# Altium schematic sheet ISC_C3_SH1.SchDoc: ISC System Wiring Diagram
size B; DrawnBy: Filiberto Clara; Engineer: Filiberto Clara; Organization: LIGO Laboratory; Address1: California Institute of Technology; Address2: Massachusetts Institute of Technology; SheetNumber: 5; SheetTotal: 39
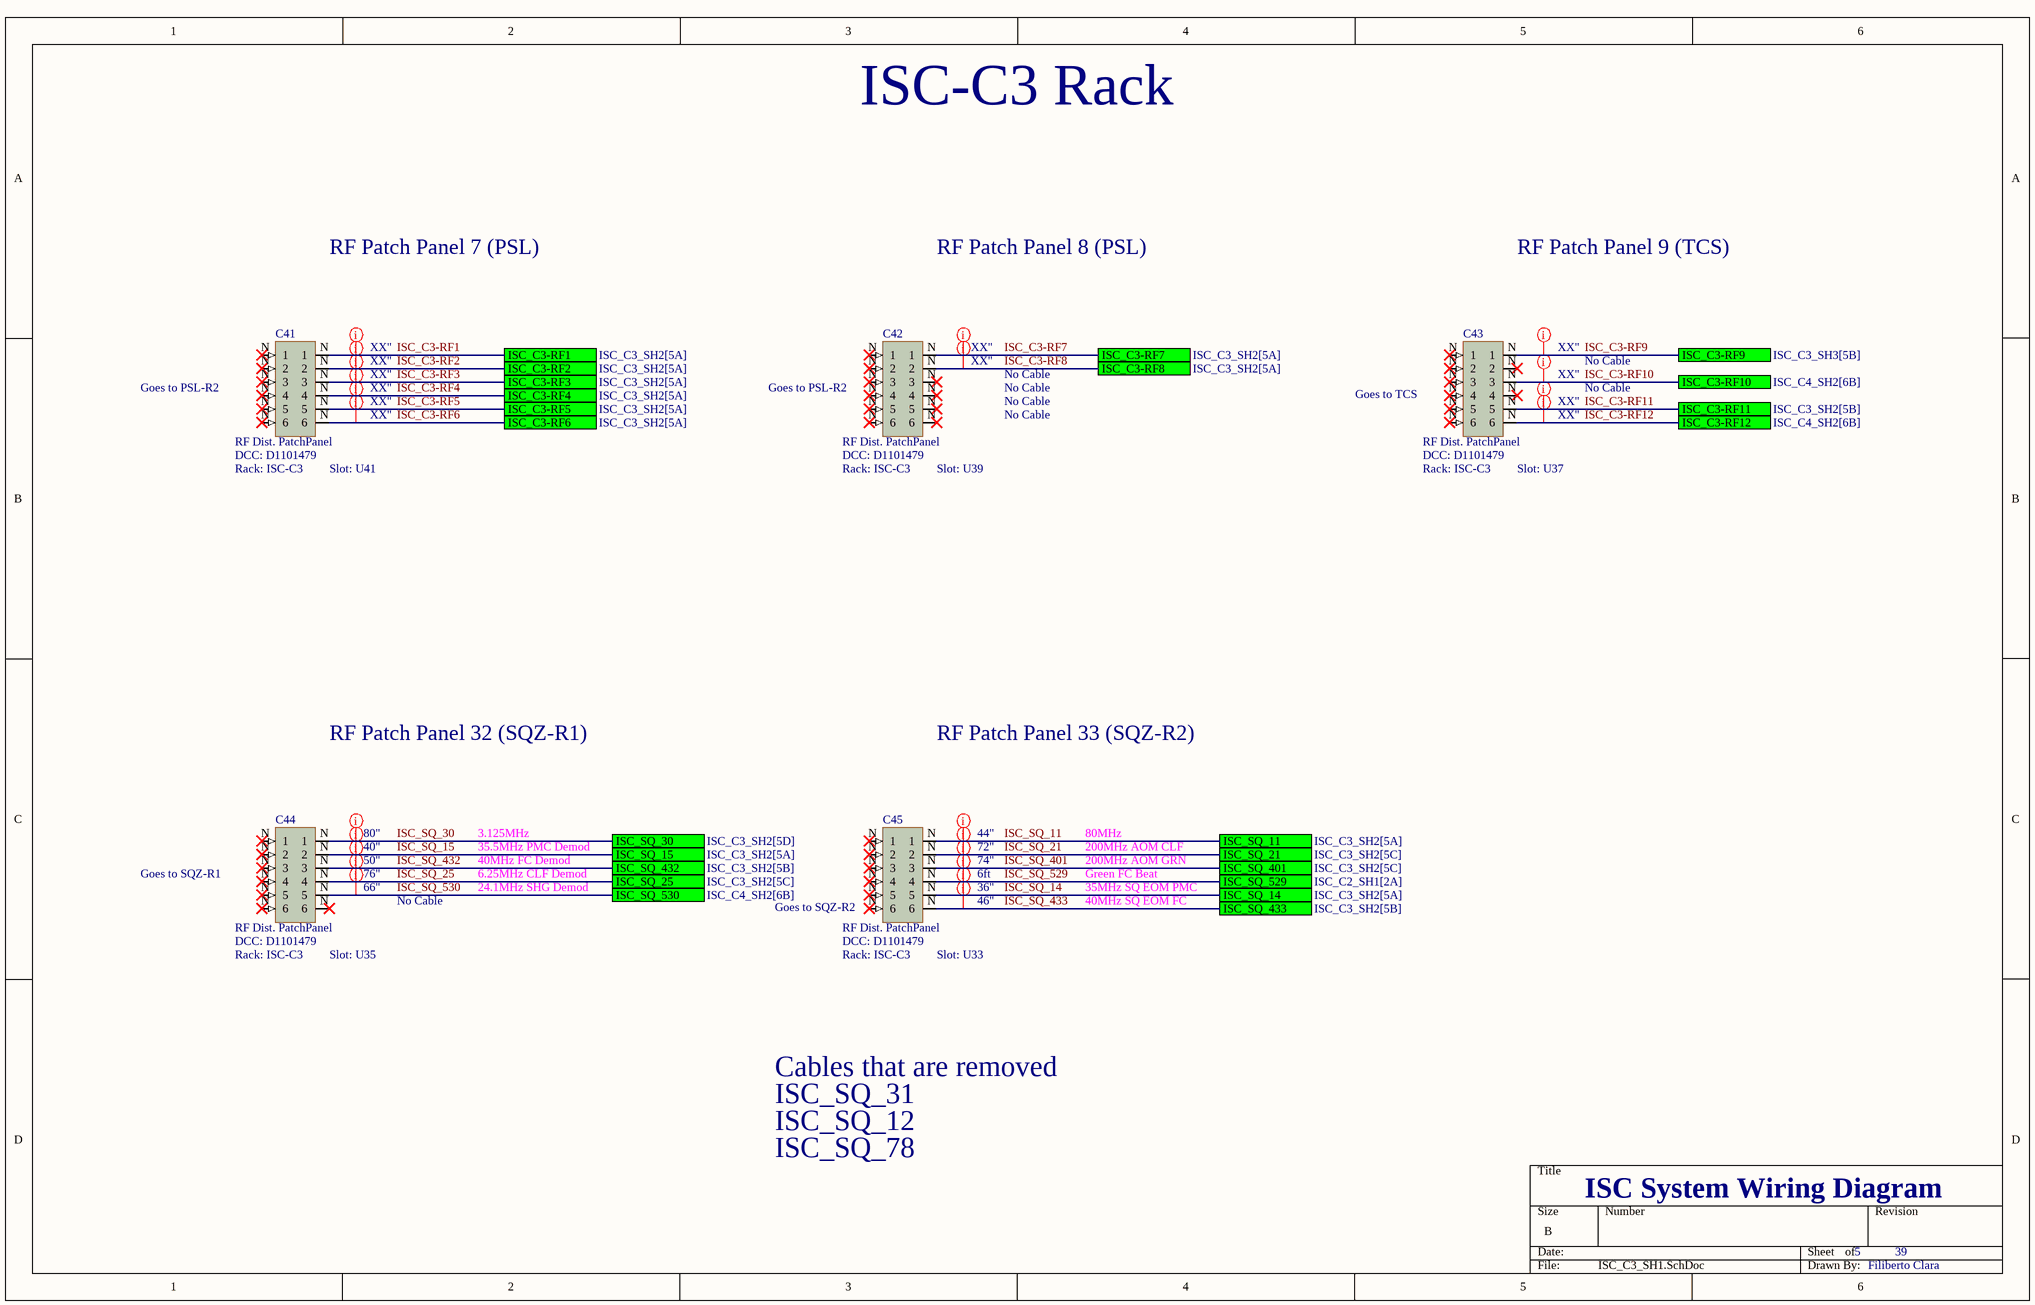
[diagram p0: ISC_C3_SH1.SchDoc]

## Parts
C41  RF Dist. PatchPanel  DCC: D1101479  Rack: ISC-C3  Slot: U41
C42  RF Dist. PatchPanel  DCC: D1101479  Rack: ISC-C3  Slot: U39
C43  RF Dist. PatchPanel  DCC: D1101479  Rack: ISC-C3  Slot: U37
C44  RF Dist. PatchPanel  DCC: D1101479  Rack: ISC-C3  Slot: U35
C45  RF Dist. PatchPanel  DCC: D1101479  Rack: ISC-C3  Slot: U33

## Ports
ISC_C3-RF1 (see ISC_C3_SH2[5A]), ISC_C3-RF2 (see ISC_C3_SH2[5A]), ISC_C3-RF3 (see ISC_C3_SH2[5A]), ISC_C3-RF4 (see ISC_C3_SH2[5A]), ISC_C3-RF5 (see ISC_C3_SH2[5A]), ISC_C3-RF6 (see ISC_C3_SH2[5A]), ISC_C3-RF7 (see ISC_C3_SH2[5A]), ISC_C3-RF8 (see ISC_C3_SH2[5A]), ISC_C3-RF9 (see ISC_C3_SH3[5B]), ISC_C3-RF10 (see ISC_C4_SH2[6B]), ISC_C3-RF11 (see ISC_C3_SH2[5B]), ISC_C3-RF12 (see ISC_C4_SH2[6B]), ISC_SQ_11 (see ISC_C3_SH2[5A]), ISC_SQ_14 (see ISC_C3_SH2[5A]), ISC_SQ_15 (see ISC_C3_SH2[5A]), ISC_SQ_21 (see ISC_C3_SH2[5C]), ISC_SQ_25 (see ISC_C3_SH2[5C]), ISC_SQ_30 (see ISC_C3_SH2[5D]), ISC_SQ_401 (see ISC_C3_SH2[5C]), ISC_SQ_432 (see ISC_C3_SH2[5B]), ISC_SQ_433 (see ISC_C3_SH2[5B]), ISC_SQ_529 (see ISC_C2_SH1[2A]), ISC_SQ_530 (see ISC_C4_SH2[6B])

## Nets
ISC_C3-RF1: C41.N(1) ; port ISC_C3-RF1
ISC_C3-RF2: C41.N(2) ; port ISC_C3-RF2
ISC_C3-RF3: C41.N(3) ; port ISC_C3-RF3
ISC_C3-RF4: C41.N(4) ; port ISC_C3-RF4
ISC_C3-RF5: C41.N(5) ; port ISC_C3-RF5
ISC_C3-RF6: C41.N(6) ; port ISC_C3-RF6
ISC_C3-RF7: C42.N(1) ; port ISC_C3-RF7
ISC_C3-RF8: C42.N(2) ; port ISC_C3-RF8
ISC_C3-RF9: C43.N(1) ; port ISC_C3-RF9
ISC_C3-RF10: C43.N(3) ; port ISC_C3-RF10
ISC_C3-RF11: C43.N(5) ; port ISC_C3-RF11
ISC_C3-RF12: C43.N(6) ; port ISC_C3-RF12
ISC_SQ_11: C45.N(1) ; port ISC_SQ_11
ISC_SQ_14: C45.N(5) ; port ISC_SQ_14
ISC_SQ_15: C44.N(2) ; port ISC_SQ_15
ISC_SQ_21: C45.N(2) ; port ISC_SQ_21
ISC_SQ_25: C44.N(4) ; port ISC_SQ_25
ISC_SQ_30: C44.N(1) ; port ISC_SQ_30
ISC_SQ_401: C45.N(3) ; port ISC_SQ_401
ISC_SQ_432: C44.N(3) ; port ISC_SQ_432
ISC_SQ_433: C45.N(6) ; port ISC_SQ_433
ISC_SQ_529: C45.N(4) ; port ISC_SQ_529
ISC_SQ_530: C44.N(5) ; port ISC_SQ_530

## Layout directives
Length: XX": ISC_C3-RF1, ISC_C3-RF2, ISC_C3-RF3, ISC_C3-RF4, ISC_C3-RF5, ISC_C3-RF6, ISC_C3-RF7, ISC_C3-RF8, ISC_C3-RF9, ISC_C3-RF10, ISC_C3-RF11, ISC_C3-RF12
Length: 36": ISC_SQ_14
Length: 44": ISC_SQ_11
Length: 80": ISC_SQ_30
Length: 66": ISC_SQ_530
Length: 50": ISC_SQ_432
Length: 76": ISC_SQ_25
Length: 72": ISC_SQ_21
Length: 74": ISC_SQ_401
Length: 46": ISC_SQ_433
Length: 6ft: ISC_SQ_529
Length: 40": ISC_SQ_15

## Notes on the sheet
- ISC-C3 Rack
- RF Patch Panel 7 (PSL)
- RF Patch Panel 8 (PSL)
- RF Patch Panel 9 (TCS)
- No Cable
- (near C41) Goes to PSL-R2
- (near C42) Goes to PSL-R2
- (near C43) Goes to TCS
- RF Patch Panel 32 (SQZ-R1)
- RF Patch Panel 33 (SQZ-R2)
- 3.125MHz
- 35.5MHz PMC Demod
- 80MHz
- 200MHz AOM CLF
- (near C44) Goes to SQZ-R1
- 24.1MHz SHG Demod
- 40MHz FC Demod
- 6.25MHz CLF Demod
- (near C45) Goes to SQZ-R2
- 200MHz AOM GRN
- 35MHz SQ EOM PMC
- 40MHz SQ EOM FC
- Green FC Beat
- Cables that are removed
- ISC_SQ_31
- ISC_SQ_12
- ISC_SQ_78

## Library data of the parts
C41-C45 = RF Dist. PatchPanel: Serial: Sxxxxxxx; System: ISC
